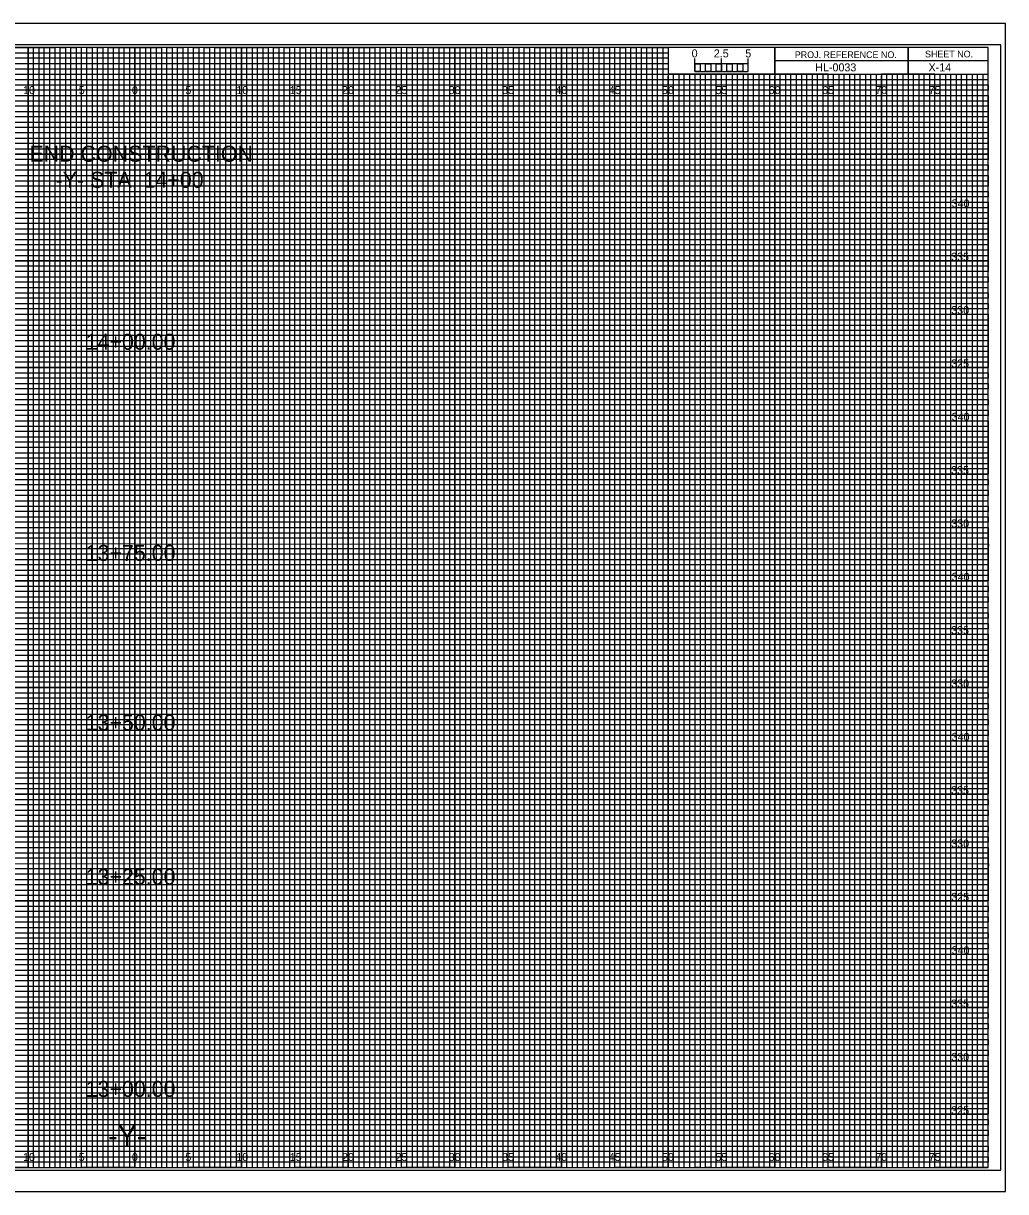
# Model space of a CAD drawing. Extents: x -7 to 162, y -2 to 107.
# Drawn here: x 69.5 to 161.7, y -2.3 to 107.3 of the extents above; entities that cross this region are included whole.
import ezdxf

# ---------------------------------------------------------------- set-up
doc = ezdxf.new("R2010")
doc.units = 0
for name, color, linetype in [('Exist XS Center Line Elevation Label', 7, 'Continuous'), ('Prop XS Alignment Label', 7, 'Continuous'), ('Prop XS Bar Scale Labels', 7, 'Continuous'), ('Prop XS Elevation Labels', 7, 'Continuous'), ('Prop XS Offset Labels', 7, 'Continuous'), ('Prop XS Project Number', 7, 'Continuous'), ('Prop XS Sheet Number', 7, 'Continuous'), ('Prop XS Station Labels', 7, 'Continuous'), ('Sheet Cross Section CELL', 7, 'Continuous'), ('Sheet Cross Section Grid Major CELL', 7, 'Continuous'), ('Sheet Cross Section Grid Middle CELL', 7, 'Continuous'), ('Sheet Cross Section Grid Minor 1 CELL', 7, 'Continuous'), ('Sheet Cross Section Grid Minor 2 CELL', 7, 'Continuous'), ('Sheet Cross Section Scale CELL', 7, 'Continuous'), ('Sheet Cutting Line CELL', 7, 'Continuous'), ('Sheet DOT Grid CELL', 7, 'Continuous'), ('Sheet Plot Border Inside CELL', 7, 'Continuous'), ('Sheet Plot Border Outside CELL', 7, 'Continuous')]:
    doc.layers.add(name, color=color, linetype=linetype)

msp = doc.modelspace()

# ---------------------------------------------------------------- linework, layer by layer
at = {"layer": 'Sheet Cross Section CELL'}
for p, q in [((152.5, 105), (152.5, 102.5)), ((152.5, 102.5), (152.5, 105)), ((160, 103.75), (140, 103.75)), ((140, 103.75), (140, 102.5)), ((140, 102.5), (160, 102.5))]:
    msp.add_line(p, q, dxfattribs=at)
for points in [[(160, 105), (0, 105), (0, 0), (160, 0)], [(140, 105), (130, 105), (130, 102.52), (140, 102.52)], [(160, 105), (140, 105), (140, 102.5), (160, 102.5)]]:
    msp.add_lwpolyline(points, close=True, dxfattribs=at)
at = {"layer": 'Sheet Cross Section Grid Major CELL'}
for p, q in [((75, 105), (70, 105)), ((70, 105), (70, 0)), ((75, 0), (75, 105)), ((85, 105), (80, 105)), ((80, 105), (80, 0)), ((85, 0), (85, 105)), ((95, 105), (90, 105)), ((90, 105), (90, 0)), ((95, 0), (95, 105)), ((105, 105), (100, 105)), ((100, 105), (100, 0)), ((105, 0), (105, 105)), ((115, 105), (110, 105)), ((110, 105), (110, 0)), ((115, 0), (115, 105)), ((125, 105), (120, 105)), ((120, 105), (120, 0)), ((125, 0), (125, 105)), ((130, 105), (130, 0)), ((135, 0), (135, 102.5)), ((145, 102.5), (140, 102.5)), ((140, 102.5), (140, 0)), ((145, 0), (145, 102.5)), ((155, 102.5), (150, 102.5)), ((150, 102.5), (150, 0)), ((155, 0), (155, 102.5)), ((70, 0), (65, 0)), ((80, 0), (75, 0)), ((90, 0), (85, 0)), ((100, 0), (95, 0)), ((110, 0), (105, 0)), ((120, 0), (115, 0)), ((130, 0), (125, 0)), ((140, 0), (135, 0)), ((150, 0), (145, 0)), ((160, 0), (155, 0)), ((160, 0), (160, 0))]:
    msp.add_line(p, q, dxfattribs=at)
for points in [[(0, 100), (160, 100), (160, 95), (0, 95)], [(0, 90), (160, 90), (160, 85), (0, 85)], [(0, 80), (160, 80), (160, 75), (0, 75)], [(0, 70), (160, 70), (160, 65), (0, 65)], [(0, 60), (160, 60), (160, 55), (0, 55)], [(0, 50), (160, 50), (160, 45), (0, 45)], [(0, 40), (160, 40), (160, 35), (0, 35)], [(0, 30), (160, 30), (160, 25), (0, 25)], [(0, 20), (160, 20), (160, 15), (0, 15)], [(0, 10), (160, 10), (160, 5), (0, 5)]]:
    msp.add_lwpolyline(points, dxfattribs=at)
at = {"layer": 'Sheet Cross Section Grid Middle CELL'}
for points in [[(67.5, 105), (72.5, 105), (72.5, 0), (77.5, 0), (77.5, 105), (82.5, 105), (82.5, 0), (87.5, 0), (87.5, 105), (92.5, 105), (92.5, 0), (97.5, 0), (97.5, 105), (102.5, 105), (102.5, 0), (107.5, 0), (107.5, 105), (112.5, 105), (112.5, 0), (117.5, 0), (117.5, 105), (122.5, 105), (122.5, 0), (127.5, 0), (127.5, 105), (129.97, 105), (130, 105), (130, 102.5), (132.5, 102.5), (132.5, 0), (137.5, 0), (137.5, 102.5), (142.5, 102.5), (142.5, 0), (147.5, 0), (147.5, 102.5), (152.5, 102.5), (152.5, 0), (157.5, 0), (157.5, 102.5)], [(0, 102.5), (137.5, 102.5)], [(0, 92.5), (160, 92.5), (160, 97.5), (0, 97.5)], [(0, 82.5), (160, 82.5), (160, 87.5), (0, 87.5)], [(0, 72.5), (160, 72.5), (160, 77.5), (0, 77.5)], [(0, 62.5), (160, 62.5), (160, 67.5), (0, 67.5)], [(0, 52.5), (160, 52.5), (160, 57.5), (0, 57.5)], [(0, 42.5), (160, 42.5), (160, 47.5), (0, 47.5)], [(0, 32.5), (160, 32.5), (160, 37.5), (0, 37.5)], [(0, 22.5), (160, 22.5), (160, 27.5), (0, 27.5)], [(0, 12.5), (160, 12.5), (160, 17.5), (0, 17.5)], [(0, 2.5), (160, 2.5), (160, 7.5), (0, 7.5)]]:
    msp.add_lwpolyline(points, dxfattribs=at)
at = {"layer": 'Sheet Cross Section Grid Minor 1 CELL'}
for p, q in [((0, 104.5), (130, 104.5)), ((130, 104.5), (130, 103.99)), ((130, 103.99), (0, 103.99)), ((0, 103.5), (130, 103.5)), ((130, 102.95), (0, 102.95)), ((130, 103.5), (130, 102.95)), ((0, 102), (160, 102))]:
    msp.add_line(p, q, dxfattribs=at)
for points in [[(0, 101.5), (135, 101.5), (160, 101.5), (160, 101), (0, 101)], [(0, 100.5), (160, 100.5), (160, 99.5), (0, 99.5)], [(0, 99), (160, 99), (160, 98.5), (0, 98.49)], [(0, 98), (160, 98), (160, 97), (0, 97)], [(0, 96.5), (160, 96.5), (160, 96), (0, 96)], [(0, 95.5), (160, 95.5), (160, 94.5), (0, 94.5)], [(0, 94), (160, 94), (160, 93.5), (0, 93.5)], [(0, 93), (160, 93), (160, 92), (0, 92)], [(0, 91.5), (160, 91.5), (160, 91), (0, 91)], [(0, 90.5), (160, 90.5), (160, 89.5), (0, 89.5)], [(0, 89), (160, 89), (160, 88.5), (0, 88.5)], [(0, 88), (160, 88), (160, 86.98), (160, 86.5), (160, 86), (0, 86)], [(0, 87), (160, 87), (160, 86.5), (0, 86.5)], [(0, 85.5), (160, 85.5), (160, 84.5), (0, 84.52)], [(0, 84.52), (160, 84.5), (160, 84), (0, 84)], [(0, 83.5), (160, 83.5), (160, 83), (0, 83)], [(0, 82), (160, 82), (160, 81.5), (0, 81.5)], [(0, 81), (160, 81), (160, 80.5), (0, 80.5)], [(-0.04, 79.45), (160, 79.45), (160, 78.94), (-0.04, 78.94)], [(0, 78.5), (160, 78.5), (160, 78), (0, 78)], [(0, 77), (160, 77), (160, 76.5), (0, 76.5)], [(0, 76), (160, 76), (160, 75.5), (0, 75.5)], [(0, 74.5), (160, 74.5), (160, 74), (0, 74)], [(0, 73.5), (160, 73.5), (160, 73), (0, 73)], [(0, 72), (160, 72), (160, 71.5), (0, 71.5)], [(0, 71), (160, 71), (160, 70.5), (0, 70.5)], [(0, 69.5), (160, 69.5), (160, 68.99), (0, 69)], [(0, 68.5), (160, 68.5), (160, 68), (0, 68)], [(0, 67), (160, 67), (160, 66.5), (0, 66.5)], [(0, 66), (160, 66), (160, 65.5), (0, 65.5)], [(0, 64.5), (160, 64.5), (160, 64), (0, 64)], [(0, 63.5), (160, 63.5), (160, 63), (0, 63)], [(0, 62), (160, 62), (160, 61.5), (0, 61.5)], [(0, 61), (160, 61), (160, 60.5), (0, 60.5)], [(0, 59.5), (160, 59.5), (160, 59), (0, 59)], [(0, 58.5), (160.03, 58.45), (160, 58), (0, 58)], [(0, 57), (160, 57), (160, 56.5), (0, 56.5)], [(0, 56), (160, 56), (160, 55.5), (0, 55.5)], [(0, 54.5), (160, 54.5), (160, 54), (0, 54)], [(0, 53.5), (160, 53.5), (160, 53), (0, 53)], [(0, 52), (160, 52), (160, 51.5), (0, 51.5)], [(0, 51), (160, 51), (160, 50.5), (0, 50.5)], [(0, 49.5), (160, 49.5), (160, 49), (0, 49)], [(0, 48.5), (160, 48.5), (160, 48), (0, 48)], [(0, 47), (160, 47), (160, 46.5), (0, 46.5)], [(0, 46), (160, 46), (160, 45.5), (0, 45.5)], [(0, 44.5), (160, 44.5), (160, 44), (0, 44)], [(0, 43.5), (160, 43.5), (160, 43), (0, 43)], [(0, 42), (160, 42), (160, 41.5), (0, 41.5)], [(0, 41), (160, 41), (160, 40.5), (0, 40.5)], [(0, 39.5), (160, 39.5), (160, 38.99), (0, 39)], [(0, 38.5), (160, 38.5), (160, 38), (0, 38)], [(0, 37), (160, 37), (160, 36.5), (0, 36.5)], [(0, 36), (160, 36), (160, 35.5), (0, 35.5)], [(0, 34.5), (160, 34.5), (160, 34), (0, 34)], [(0, 33.5), (160, 33.5), (160, 33), (0, 33)], [(0, 32), (160, 32), (160, 31.5), (0, 31.5)], [(0, 31), (160, 31), (160, 30.5), (0, 30.5)], [(0, 29.5), (160, 29.5), (160, 29), (0, 29)], [(0, 28.5), (160.03, 28.46), (160, 28), (0, 28)], [(0, 27), (160, 27), (160, 26.5), (0, 26.5)], [(0, 26), (160, 26), (160, 25.5), (0, 25.5)], [(0, 24.5), (160, 24.5), (160, 24), (0, 24)], [(0, 23.5), (160, 23.5), (160, 23), (0, 23)], [(0, 22), (160, 22), (160, 21.5), (0, 21.5)], [(0, 21), (160, 21), (160, 20.5), (0, 20.5)], [(0, 19.5), (160, 19.5), (160, 19), (0, 19)], [(0, 18.5), (160, 18.5), (160, 18), (0, 18)], [(0, 17), (160, 17), (160, 16.5), (0, 16.5)], [(0, 16), (160, 16), (160, 15.5), (0, 15.5)], [(0, 14.5), (160, 14.5), (160, 14), (0, 14)], [(0, 13.5), (160, 13.5), (160, 13), (0, 13)], [(0, 12), (160, 12), (160, 11.5), (0, 11.5)], [(0, 11), (160, 11), (160, 10.5), (0, 10.5)], [(0, 9.5), (160, 9.5), (160, 9), (0, 9)], [(0, 8.5), (160, 8.5), (160, 8), (0, 8)], [(0, 7), (160, 7), (160, 6.5), (0, 6.5)], [(0, 6), (160, 6), (160, 5.5), (0, 5.5)], [(0, 4.5), (160, 4.5), (160, 4), (0, 4)], [(0, 3.5), (160, 3.5), (160, 3), (0, 3)], [(0, 2), (160, 2), (160, 1.5), (0, 1.5)], [(0, 1), (160, 1), (160, 0.5), (0, 0.5)]]:
    msp.add_lwpolyline(points, dxfattribs=at)
at = {"layer": 'Sheet Cross Section Grid Minor 2 CELL'}
for p, q in [((133.5, 102.5), (133, 102.5)), ((133, 102.5), (133, 0)), ((133.5, 0), (133.5, 102.5)), ((134.5, 102.5), (134, 102.5)), ((134, 102.5), (134, 0)), ((134.5, 0), (134.5, 102.5)), ((133, 0), (132.5, 0)), ((134, 0), (133.5, 0))]:
    msp.add_line(p, q, dxfattribs=at)
for points in [[(70, 0), (70.5, 0), (70.5, 105), (71, 105), (71, 0)], [(71, 0), (71.5, 0), (71.5, 105), (72, 105), (72, 0)], [(72.5, 0), (73, 0), (73, 105), (73.5, 105), (73.5, 0)], [(73.5, 0), (74, 0), (74, 105), (74.5, 105), (74.5, 0)], [(75, 0), (75.5, 0), (75.5, 105), (76, 105), (76, 0)], [(76, 0), (76.5, 0), (76.5, 105), (77, 105), (77, 0)], [(77.5, 0), (78, 0), (78, 105), (78.5, 105), (78.5, 0)], [(78.5, 0), (79, 0), (79, 105), (79.5, 105), (79.5, 0)], [(80, 0), (80.5, 0), (80.5, 105), (81, 105), (81, 0)], [(81, 0), (81.5, 0), (81.5, 105), (82, 105), (82, 0)], [(82.5, 0), (83, 0), (83, 105), (83.5, 105), (83.5, 0)], [(83.5, 0), (84, 0), (84, 105), (84.5, 105), (84.5, 0)], [(85, 0), (85.5, 0), (85.5, 105), (86, 105), (86, 0)], [(86, 0), (86.5, 0), (86.5, 105), (87, 105), (87, 0)], [(87.5, 0), (88, 0), (88, 105), (88.5, 105), (88.5, 0)], [(88.5, 0), (89, 0), (89, 105), (89.5, 105), (89.5, 0)], [(90, 0), (90.5, 0), (90.5, 105), (91, 105), (91, 0)], [(91, 0), (91.5, 0), (91.5, 105), (92, 105), (92, 0)], [(92.5, 0), (93, 0), (93, 105), (93.5, 105), (93.5, 0)], [(93.5, 0), (94, 0), (94, 105), (94.5, 105), (94.5, 0)], [(95, 0), (95.5, 0), (95.5, 105), (96, 105), (96, 0)], [(96, 0), (96.5, 0), (96.5, 105), (97, 105), (97, 0)], [(97.5, 0), (98, 0), (98, 105), (98.5, 105), (98.5, 0)], [(98.5, 0), (99, 0), (99, 105), (99.5, 105), (99.5, 0)], [(100, 0), (100.5, 0), (100.5, 105), (101, 105), (101, 0)], [(101, 0), (101.5, 0), (101.5, 105), (102, 105), (102, 0)], [(102.5, 0), (103, 0), (103, 105), (103.5, 105), (103.5, 0)], [(103.5, 0), (104, 0), (104, 105), (104.5, 105), (104.5, 0)], [(105, 0), (105.5, 0), (105.5, 105), (106, 105), (106, 0)], [(106, 0), (106.5, 0), (106.5, 105), (107, 105), (107, 0)], [(107.5, 0), (108, 0), (108, 105), (108.5, 105), (108.5, 0)], [(108.5, 0), (109, 0), (109, 105), (109.5, 105), (109.5, 0)], [(110, 0), (110.5, 0), (110.5, 105), (111, 105), (111, 0)], [(111, 0), (111.5, 0), (111.5, 105), (112, 105), (112, 0)], [(112.5, 0), (113, 0), (113, 105), (113.5, 105), (113.5, 0)], [(113.5, 0), (114, 0), (114, 105), (114.5, 105), (114.5, 0)], [(115, 0), (115.5, 0), (115.5, 105), (116, 105), (116, 0)], [(116, 0), (116.5, 0), (116.5, 105), (117, 105), (117, 0)], [(117.5, 0), (118, 0), (118, 105), (118.5, 105), (118.5, 0)], [(118.5, 0), (119, 0), (119, 105), (119.5, 105), (119.5, 0)], [(120, 0), (120.5, 0), (120.5, 105), (121, 105), (121, 0)], [(121, 0), (121.5, 0), (121.5, 105), (122, 105), (122, 0)], [(122.5, 0), (123, 0), (123, 105), (123.5, 105), (123.5, 0)], [(123.5, 0), (124, 0), (124, 105), (124.5, 105), (124.5, 0)], [(125, 0), (125.5, 0), (125.5, 105), (126, 105), (126, 0)], [(126, 0), (126.5, 0), (126.5, 105), (127, 105), (127, 0)], [(127.5, 0), (128, 0), (128, 105), (128.5, 105), (128.5, 0)], [(128.5, 0), (129, 0), (129, 105), (129.5, 105), (129.5, 0)], [(130, 0), (130.5, 0), (130.5, 102.5), (131.01, 102.5), (131.01, 0)], [(131, 0), (131.5, 0), (131.5, 102.5), (132, 102.5), (132, 0)], [(135, 0), (135.49, 0), (135.49, 102.5), (136, 102.5), (136, 0)], [(136, 0), (136.5, 0), (136.5, 102.5), (137.03, 102.5), (137.03, 0)], [(137.5, 0), (138, 0), (138, 102.5), (138.5, 102.5), (138.5, 0)], [(138.5, 0), (139, 0), (139, 102.5), (139.5, 102.5), (139.5, 0)], [(140, 0), (140.5, 0), (140.5, 102.5), (141, 102.5), (141, 0)], [(141, 0), (141.5, 0), (141.5, 102.5), (142, 102.5), (142, 0)], [(142.5, 0), (143, 0), (143, 102.5), (143.5, 102.5), (143.5, 0)], [(143.5, 0), (144, 0), (144, 102.5), (144.5, 102.5), (144.5, 0)], [(145, 0), (145.5, 0), (145.5, 102.5), (146, 102.5), (146, 0)], [(146, 0), (146.5, 0), (146.5, 102.5), (147, 102.5), (147, 0)], [(147.5, 0), (148, 0), (148, 102.5), (148.5, 102.5), (148.5, 0)], [(148.5, 0), (149, 0), (149, 102.5), (149.5, 102.5), (149.5, 0)], [(150, 0), (150.5, 0), (150.5, 102.5), (151, 102.5), (151, 0)], [(151, 0), (151.5, 0), (151.5, 102.5), (152, 102.5), (152, 0)], [(152.5, 0), (153, 0), (153, 102.5), (153.5, 102.5), (153.5, 0)], [(153.5, 0), (154, 0), (154, 102.5), (154.5, 102.5), (154.5, 0)], [(155, 0), (155.5, 0), (155.5, 102.5), (156, 102.5), (156, 0)], [(156, 0), (156.5, 0), (156.5, 102.5), (157, 102.5), (157, 0)], [(157.5, 0), (158, 0), (158, 102.5), (158.5, 102.5), (158.5, 0)], [(158.5, 0), (159, 0), (159, 102.5), (159.5, 102.5), (159.5, 0)]]:
    msp.add_lwpolyline(points, dxfattribs=at)
at = {"layer": 'Sheet Cross Section Scale CELL'}
for p, q in [((132.5, 102.75), (132.5, 103.95)), ((132.5, 103.45), (132.5, 103.95)), ((135, 102.75), (135, 103.95)), ((137.5, 102.75), (137.5, 103.95)), ((137.5, 103.45), (137.5, 103.95))]:
    msp.add_line(p, q, dxfattribs=at)
for points in [[(137.5, 103.45), (132.5, 103.45), (132.5, 102.75), (137.5, 102.75)], [(132.5, 103.45), (133, 103.45), (133, 102.75), (132.5, 102.75)], [(133.5, 103.45), (134, 103.45), (134, 102.75), (133.5, 102.75)], [(134.5, 103.45), (135, 103.45), (135, 102.75), (134.5, 102.75)], [(135.5, 103.45), (136, 103.45), (136, 102.75), (135.5, 102.75)], [(136.5, 103.45), (137, 103.45), (137, 102.75), (136.5, 102.75)]]:
    msp.add_lwpolyline(points, close=True, dxfattribs=at)
at = {"layer": 'Sheet Cutting Line CELL'}
for p, q in [((161.65, 107.25), (-6.7, 107.25)), ((-6.7, -2.25), (161.65, -2.25))]:
    msp.add_line(p, q, dxfattribs=at)
at = {"layer": 'Sheet DOT Grid CELL'}
for p, q in [((70, 0), (70, 105)), ((75, 0), (75, 105)), ((80, 0), (80, 105)), ((85, 0), (85, 105)), ((90, 0), (90, 105)), ((95, 0), (95, 105)), ((100, 0), (100, 105)), ((105, 0), (105, 105)), ((110, 0), (110, 105)), ((115, 0), (115, 105)), ((120, 0), (120, 105)), ((125, 0), (125, 105)), ((130, 0), (130, 102.34)), ((135, 0), (135, 102.34)), ((140, 0), (140, 102.34)), ((145, 0), (145, 102.34)), ((150, 0), (150, 102.34)), ((155, 0), (155, 102.34)), ((0, 100), (160, 100)), ((0, 95), (160, 95)), ((0, 90), (160, 90)), ((0, 85), (160, 85)), ((0, 80), (160, 80)), ((0, 75), (160, 75)), ((0, 70), (160, 70)), ((0, 65), (160, 65)), ((0, 60), (160, 60)), ((0, 55), (160, 55)), ((0, 50), (160, 50)), ((0, 45), (160, 45)), ((0, 40), (160, 40)), ((0, 35), (160, 35)), ((0, 30), (160, 30)), ((0, 25), (160, 25)), ((0, 20), (160, 20)), ((0, 15), (160, 15)), ((0, 10), (160, 10)), ((0, 5), (160, 5))]:
    msp.add_line(p, q, dxfattribs=at)
at = {"layer": 'Sheet Plot Border Inside CELL'}
msp.add_lwpolyline([(-5.4, -0.25), (161.2, -0.25), (161.2, 105.25), (-5.4, 105.25)], close=True, dxfattribs=at)
at = {"layer": 'Sheet Plot Border Outside CELL'}
msp.add_lwpolyline([(-6.7, -2.25), (161.65, -2.25), (161.65, 107.25), (-6.7, 107.25)], close=True, dxfattribs=at)

# ---------------------------------------------------------------- texts
at = {"layer": 'Exist XS Center Line Elevation Label'}
for s, p in [('END CONSTRUCTION', (70.12, 94.28)), ('-Y- STA. 14+00', (72.57, 91.84))]:
    msp.add_text(s, height=1.5, dxfattribs=at).set_placement(p)
at = {"layer": 'Prop XS Alignment Label'}
msp.add_text('-Y-', height=2, dxfattribs=at).set_placement((77.5, 2))
at = {"layer": 'Prop XS Bar Scale Labels'}
for s, p in [('2.5', (134.29, 104.06)), ('5', (137.24, 104.06))]:
    msp.add_text(s, height=0.75, dxfattribs=at).set_placement(p)
at = {"layer": 'Prop XS Elevation Labels'}
for s, p in [('340', (156.59, 90)), ('335', (156.54, 85)), ('330', (156.55, 80)), ('325', (156.55, 75)), ('340', (156.59, 70)), ('335', (156.54, 65)), ('330', (156.55, 60)), ('340', (156.59, 55)), ('335', (156.54, 50)), ('330', (156.55, 45)), ('340', (156.59, 40)), ('335', (156.54, 35)), ('330', (156.55, 30)), ('325', (156.55, 25)), ('340', (156.59, 20)), ('335', (156.54, 15)), ('330', (156.55, 10)), ('325', (156.55, 5))]:
    msp.add_text(s, height=0.75, dxfattribs=at).set_placement(p)
at = {"layer": 'Prop XS Offset Labels'}
for s, p in [('10', (69.52, 100.62)), ('5', (74.74, 100.62)), ('0', (79.73, 100.62)), ('0', (79.73, 100.62)), ('5', (84.74, 100.62)), ('10', (89.52, 100.62)), ('15', (94.53, 100.62)), ('20', (99.43, 100.62)), ('25', (104.44, 100.62)), ('30', (109.43, 100.62)), ('35', (114.44, 100.62)), ('40', (119.43, 100.62)), ('45', (124.44, 100.62)), ('50', (129.43, 100.62)), ('55', (134.44, 100.62)), ('60', (139.43, 100.62)), ('65', (144.44, 100.62)), ('70', (149.43, 100.62)), ('75', (154.44, 100.62)), ('10', (69.52, 0.62)), ('5', (74.74, 0.62)), ('0', (79.73, 0.62)), ('0', (79.73, 0.62)), ('5', (84.74, 0.62)), ('10', (89.52, 0.62)), ('15', (94.53, 0.62)), ('20', (99.43, 0.62)), ('25', (104.44, 0.62)), ('30', (109.43, 0.62)), ('35', (114.44, 0.62)), ('40', (119.43, 0.62)), ('45', (124.44, 0.62)), ('50', (129.43, 0.62)), ('55', (134.44, 0.62)), ('60', (139.43, 0.62)), ('65', (144.44, 0.62)), ('70', (149.43, 0.62)), ('75', (154.44, 0.62))]:
    msp.add_text(s, height=0.75, dxfattribs=at).set_placement(p)
at = {"layer": 'Prop XS Project Number'}
msp.add_text('HL-0033', height=0.75, dxfattribs=at).set_placement((143.8, 102.75))
at = {"layer": 'Prop XS Sheet Number'}
msp.add_text('X-14', height=0.75, dxfattribs=at).set_placement((154.42, 102.75))
at = {"layer": 'Prop XS Station Labels'}
for s, p in [('14+00.00', (75.39, 76.66)), ('13+75.00', (75.39, 56.87)), ('13+50.00', (75.39, 40.97)), ('13+25.00', (75.39, 26.52)), ('13+00.00', (75.39, 6.63))]:
    msp.add_text(s, height=1.5, dxfattribs=at).set_placement(p)
at = {"layer": 'Sheet Cross Section CELL'}
for s, p in [('PROJ. REFERENCE NO.', (141.88, 104)), ('SHEET NO.', (154.09, 104.06))]:
    msp.add_text(s, height=0.625, dxfattribs=at).set_placement(p)
at = {"layer": 'Sheet Cross Section Scale CELL'}
msp.add_text('0', height=0.75, dxfattribs=at).set_placement((132.21, 104.06))

doc.saveas('drawing.dxf')
